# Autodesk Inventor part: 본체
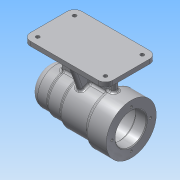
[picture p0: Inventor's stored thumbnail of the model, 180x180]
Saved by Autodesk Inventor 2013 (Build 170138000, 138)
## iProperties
Created: 2016-06
Part Number: 본체
Material: 알루미늄 6061
Document SubType Name: Modeling
Designer: Administrator
Density: 2.71 g/cm^3
Mass: 673.897 g
Surface Area: 647.23 cm^2
Volume: 248.671 cm^3
Author: Administrator
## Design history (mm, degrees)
sketch "스케치1"
  geometry: L1 (0, 0)-(0, 25); L2 (0, 25)-(25, 25); L3 (25, 25)-(25, 27); L4 (25, 27)-(45, 27); L5 (45, 27)-(45, 30); L6 (45, 30)-(84, 30); L7 (84, 30)-(84, 34); L8 (84, 34)-(112, 34); L9 (112, 34)-(112, 0); L10 (0, 0)-(112, 0)
  constraints: 20 end point, 6 perpendicular, 3 parallel, 1 vertical
  dimensions: "d0" = 25 distance of L1.start L1.end; "d1" = 25 distance of L1.end L2.end; "d2" = 2 distance of L2.end L3.end; "d3" = 20 distance of L3.end L4.end; "d4" = 3 distance of L4.end L5.end; "d5" = 39 distance of L5.end L6.end; "d6" = 4 distance of L6.end L7.end; "d7" = 28 distance of L7.end L8.end
revolve "회전1" sketch "스케치1" stored, may be unused: angle "d8" = 90 deg
sketch "스케치2"
  geometry: C1 r 34 at (0, 0) reference; C2 r 21 at (0, 0)
  constraints: 1 centre point, 1 coincident
  dimensions: "d9" = 42 diameter of C2
extrude "돌출1" cut sketch "스케치2" distance "d10" = 15; taper "d11" = 0 deg
sketch "스케치3"
  geometry: C1 r 21 at (0, 0) reference; C2 r 24 at (0, 0)
  constraints: 1 centre point, 1 coincident
  dimensions: "d12" = 48 diameter of C2
extrude "돌출2" cut sketch "스케치3" distance "d13" = 54; taper "d14" = 0 deg
sketch "스케치4"
  geometry: C1 r 24 at (0, 0) reference; C2 r 21 at (0, 0)
  constraints: 1 centre point, 1 coincident
  dimensions: "d15" = 42 diameter of C2
extrude "돌출3" cut sketch "스케치4" distance "d16" = 12; taper "d17" = 0 deg
sketch "스케치5"
  geometry: C1 r 21 at (0, 0) reference; C2 r 17.5 at (0, 0)
  constraints: 1 centre point, 1 coincident
  dimensions: "d18" = 35 diameter of C2
extrude "돌출4" cut sketch "스케치5" distance "d19" = 18; taper "d20" = 0 deg
sketch "스케치6"
  geometry: C1 r 17.5 at (0, 0) reference; C2 r 16 at (0, 0)
  constraints: 1 centre point, 1 coincident
  dimensions: "d21" = 32 diameter of C2
extrude "돌출5" cut sketch "스케치6" distance "d22" = 4; taper "d23" = 0 deg
sketch "스케치7"
  geometry: C1 r 16 at (0, 0) reference; C2 r 10.5 at (0, 0)
  constraints: 1 centre point, 1 coincident
  dimensions: "d24" = 21 diameter of C2
extrude "돌출6" cut sketch "스케치7" distance "d25" = 3; taper "d26" = 0 deg
fillet "모깎기1" dims "d27" = 3
sketch "스케치8"
  geometry: 1 further point
fillet "모깎기2" dims "d28" = 3
sketch "스케치9"
  geometry: 1 further point
fillet "모깎기3" dims "d29" = 0.3
sketch "스케치10"
  geometry: 1 further point
sketch "스케치11" dims "d30" = 52
  geometry: L1 (0, 0)-(0, 26); C1 r 34 at (0, 0) reference; 1 further point
  constraints: 2 coincident, 2 end point, 1 vertical, 1 vertical alignment, 2 other
hole "구멍1" sketch "스케치11" at (0, 26) diameter "d31" = 3.242; stored, may be unused: countersink angle "d35" = 90 deg, drill point angle "d37" = 118 deg; dims "d32" = 8, "d33" = 4, "d34" = 2, "d36" = 11
chamfer "모따기1" distance "d41" = 1; stored, may be unused: second distance "d42" = 2, angle "d43" = 45 deg
fillet "모깎기4" dims "d44" = 10
fillet "모깎기5" dims "d45" = 3
node "작업 평면1"
sketch "스케치12"
  geometry: L1 (0, 15)-(0, -15) reference; L2 (-112, 34)-(-112, -34) reference; L3 (0, 0)-(0, 35); L4 (0, 35)-(-112, 35); L5 (-112, 35)-(-112, -35); L6 (-112, -35)-(0, -35); L7 (0, -35)-(0, 0)
  constraints: 10 end point, 2 parallel, 2 perpendicular, 1 point on line
  dimensions: "d47" = 35 distance of L3.start L3.end; "d48" = 112 distance of L3.end L4.end; "d49" = 70 distance of L4.end L5.end
extrude "돌출7" join sketch "스케치12" distance "d50" = 10; taper "d51" = 0 deg
sketch "스케치13"
  geometry: L1 (0, 35)-(-112, 35) reference; L2 (-112, -35)-(0, -35) reference; L3 (-56, -35)-(-56, 35); L4 (-20, 4)-(-92, 4); L5 (-92, 4)-(-92, -4); L6 (-92, -4)-(-20, -4); L7 (-20, -4)-(-20, 4); L8 (-20, 4)-(-92, -4); L9 (-92, 4)-(-20, -4); 2 further points
  constraints: 14 end point, 5 midpoint, 2 parallel, 1 horizontal, 1 perpendicular
  dimensions: "d54" = 8 distance of L5.end L4.end; "d56" = 6.34019 deg angle of L1 L8
extrude "돌출8" join sketch "스케치13" stored distance "d57" = 10; taper "d58" = 0 deg
node "작업 평면2"
sketch "스케치14"
  geometry: L1 (-35, 70)-(-35, 60) reference; L2 (35, 60)-(-35, 60) reference; L3 (-35, 60)-(-28, 60); L4 (-28, 60)-(-16.9, 29.502); 2 further points
  constraints: 4 end point, 1 point on line, 2 other
  dimensions: "d60" = 7 distance of L1.end L3.end; "d61" = 110 deg angle of L3 L4
feature "리브1" sketch "스케치14" dims "d62" = 1, "d63" = 8, "d64" = 0, "d65" = 0, "d66" = 1, "d67" = 1
fillet "모깎기6" dims "d68" = 3
fillet "모깎기7" dims "d69" = 10
sketch "스케치15"
  geometry: C1 r 4.5 at (-102, -25); C2 r 4.5 at (-102, 25); A1 r 10 centre (-102, -25) between (-112, -25) and (-102, -35) reference; A2 r 10 centre (-102, 25) between (-102, 35) and (-112, 25) reference; 1 further point
  constraints: 2 centre point, 2 coincident
  dimensions: "d70" = 9 diameter of C1; "d71" = 9 diameter of C2
extrude "돌출9" cut sketch "스케치15" distance "d72" = 4; taper "d73" = 0 deg
sketch "스케치16"
  geometry: C1 r 4.5 at (0, 0) reference; C2 r 2.5 at (0, 0); 1 further point
  constraints: 1 centre point, 1 coincident
  dimensions: "d74" = 5 diameter of C2
extrude "돌출10" cut sketch "스케치16" stored distance "d75" = 4; taper "d76" = 0 deg
sketch "스케치17"
  geometry: C1 r 4.5 at (0, 0) reference; C2 r 2.5 at (0, 0); 1 further point
  constraints: 1 centre point, 1 coincident
  dimensions: "d77" = 5 diameter of C2
extrude "돌출11" cut sketch "스케치17" stored distance "d78" = 4; taper "d79" = 0 deg
node "작업 평면3"
chamfer "모따기2" distance "d81" = 4; stored, may be unused: second distance "d82" = 2, angle "d83" = 45 deg
fillet "모깎기8" dims "d84" = 3
node "작업 평면4"
sketch "스케치18"
  geometry: L1 (17.304, -30)-(17.304, 29.317) reference; L2 (54.5, 70)-(-37.5, 70) reference; L3 (-47.5, 34)-(-47.5, -34) reference; 2 further points
  constraints: 1 other
  dimensions: "d85" = 70 distance from line of point (0.5, 0) L2; "d86" = 48 distance from line of point (0.5, 0) L3
feature "엠보싱1" sketch "스케치18" dims "d87" = 0.5, "d88" = 0
sketch "스케치19"
  geometry: L1 (0, 0)-(25, 0); L2 (0, 0)-(45, 0); L3 (0, 0)-(84, 0)
  constraints: 6 end point, 1 collinear, 1 horizontal, 1 point on line
  dimensions: "d89" = 25 distance of L1.start L1.end; "d90" = 45 distance of L1.start L2.end; "d91" = 84 distance of L1.start L3.end
node "솔리드1"
pattern_circular "원형 패턴1" dims angle "d39" = 360 deg
mirror "대칭1"
mirror "대칭2"
other parameters: "d59" = 56, "d80" = 56
